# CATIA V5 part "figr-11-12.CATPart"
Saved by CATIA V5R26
Part number: Part1
Bounding box of the stored display mesh (mm): x -10 to 5, y -10.258 to 7.91, z -1.851 to 2.054
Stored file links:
  D:\_Deepak\CATIA\CATIA V5-6R2016_Deepak\Resources\Part files\Partfiles\c11_catia_v5_6r2016_prt\figr-11-12.CATPart
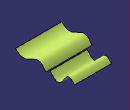
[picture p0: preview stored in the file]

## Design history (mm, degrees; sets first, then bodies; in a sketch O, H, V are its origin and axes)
Set1
  Sketch1 on yz-plane, origin (0, 0, 0), H (0, 1, 0), V (0, 0, 1)
    spline S1 through (-0.358, 0) (-3.1664, 2.0538) (-6.7822, 0.4079) (-10.2576, 1.6423)
    point P1 (-0.358, 0)
    coincidence: P1 H
  Extrude1: Element1 Sketch1, Lim1 5, Lim2 10, Direction yz-plane
  Sketch2 on yz-plane, origin (0, 0, 0), H (0, 1, 0), V (0, 0, 1)
    spline S1 through (0, 0) (3.5471, -1.4404) (5.7957, 1.2855) (7.9098, 0)
    point P1 (0, 0)
    point P2 (7.9098, 0)
    coincidence: P1 O, P2 H
  Extrude2: Element1 Sketch2, Lim1 4, Lim2 8, Direction yz-plane
Body1 (main body)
